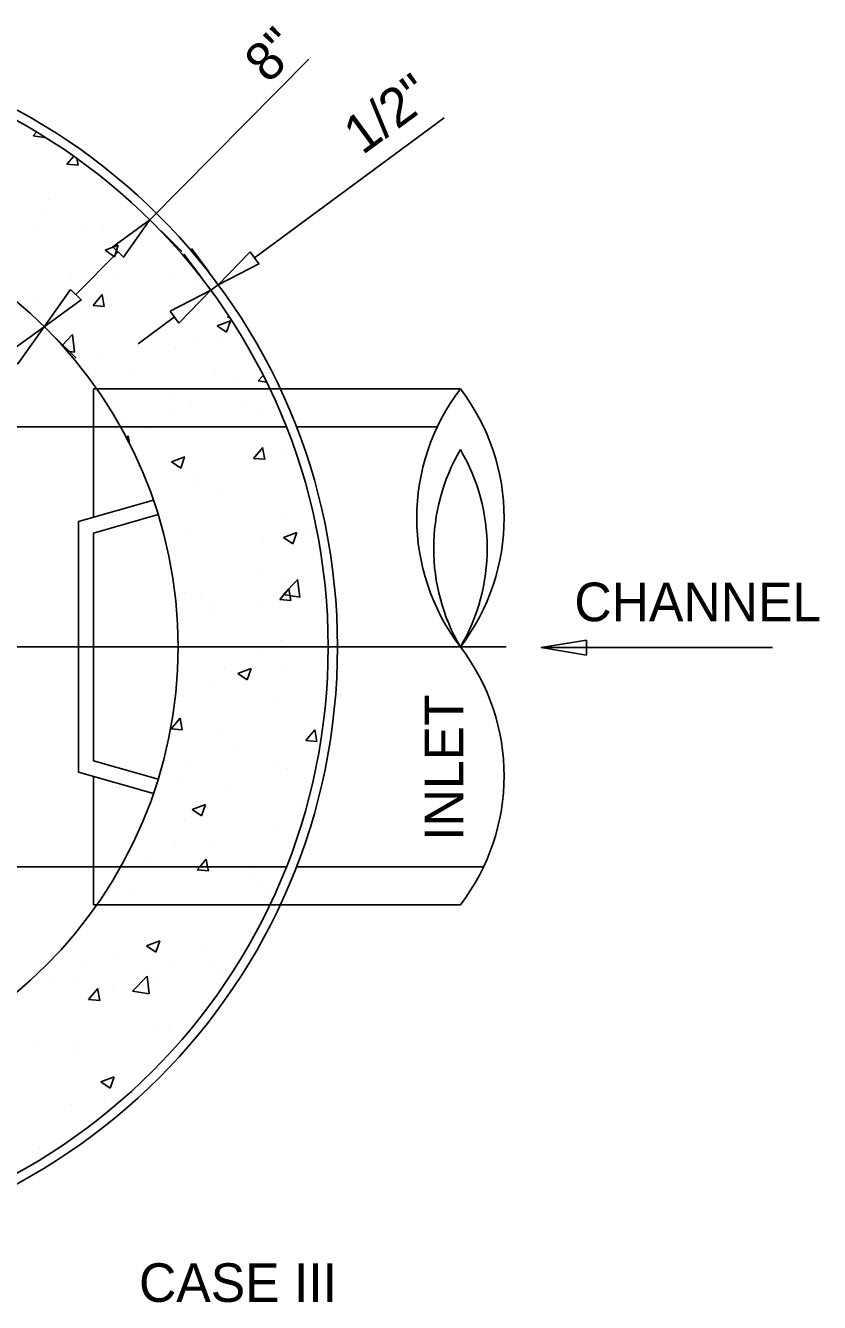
# Model space of a CAD drawing. Extents: x 6712067 to 6713867, y 1867712 to 1869162.
# Drawn here: x 6713040.8 to 6713164.1, y 1867921.8 to 1868120.1 of the extents above; entities that cross this region are included whole.
import ezdxf

# ---------------------------------------------------------------- set-up
doc = ezdxf.new("R2010")
doc.units = 0
for name, color, linetype in [('G-MARK', 7, 'Continuous'), ('G-TEXT', 7, 'Continuous'), ('Misc CnstDet(22)', 7, 'Continuous')]:
    doc.layers.add(name, color=color, linetype=linetype)

msp = doc.modelspace()

# ---------------------------------------------------------------- linework, layer by layer
at = {"layer": 'G-MARK'}
for p, q in [((6713084.83, 1868114.93), (6713060.12, 1868089.94)), ((6713076.38, 1868084.03), (6713105.86, 1868105.8)), ((6713048.64, 1868078.33), (6713055.2, 1868084.97)), ((6713063.95, 1868074.86), (6713058.33, 1868070.7)), ((6713120.94, 1868023.49), (6713156.86, 1868023.49))]:
    msp.add_line(p, q, dxfattribs=at)
at = {"layer": 'G-TEXT'}
for points in [[(6713054.37, 1868085.78), (6713056.02, 1868084.14), (6713060.12, 1868089.94)], [(6713075.69, 1868084.97), (6713077.07, 1868083.1), (6713070.76, 1868079.87)], [(6713047.82, 1868079.15), (6713049.47, 1868077.51), (6713043.72, 1868073.35)], [(6713063.26, 1868075.79), (6713064.64, 1868073.92), (6713069.58, 1868079.01)], [(6713037.97, 1868069.2), (6713039.63, 1868067.56), (6713043.72, 1868073.35)], [(6713127.94, 1868022.32), (6713120.94, 1868023.49), (6713127.94, 1868024.65)]]:
    msp.add_lwpolyline(points, close=True, dxfattribs=at)
at = {"layer": 'Misc CnstDet(22)'}
for p, q in [((6713041.98, 1868102.99), (6713042.54, 1868103.58)), ((6713041.98, 1868102.99), (6713044.02, 1868102.67)), ((6713047.24, 1868098.58), (6713048.3, 1868099.84)), ((6713047.24, 1868098.58), (6713048.99, 1868098.43)), ((6713048.99, 1868098.43), (6713048.79, 1868099.48)), ((6713044.31, 1868093.16), (6713044.31, 1868093.16)), ((6713043.38, 1868091.3), (6713043.38, 1868091.3)), ((6713060.12, 1868089.94), (6713060.12, 1868089.94)), ((6713060.12, 1868089.94), (6713060.12, 1868089.94)), ((6713042.67, 1868088.25), (6713042.67, 1868088.25)), ((6713049.96, 1868089.2), (6713049.96, 1868089.2)), ((6713052.97, 1868088.41), (6713052.97, 1868088.41)), ((6713061.86, 1868088.22), (6713065.09, 1868085.03)), ((6713053.19, 1868085.22), (6713055.22, 1868086)), ((6713054.64, 1868084.23), (6713055.22, 1868086)), ((6713053.19, 1868085.22), (6713054.64, 1868084.23)), ((6713068.13, 1868080.97), (6713065.42, 1868084.64)), ((6713069.3, 1868081.85), (6713066.6, 1868085.51)), ((6713047.92, 1868081.6), (6713047.92, 1868081.6)), ((6713054.51, 1868081.1), (6713054.51, 1868081.1)), ((6713063.48, 1868080.94), (6713063.48, 1868080.94)), ((6713067.35, 1868080.57), (6713067.35, 1868080.57)), ((6713069.58, 1868079.01), (6713070.76, 1868079.87)), ((6713070.76, 1868079.87), (6713070.76, 1868079.87)), ((6713070.76, 1868079.87), (6713070.76, 1868079.87)), ((6713051.3, 1868076.66), (6713052.7, 1868078.33)), ((6713052.63, 1868078.7), (6713052.63, 1868078.7)), ((6713053.04, 1868076.5), (6713052.7, 1868078.33)), ((6713053.34, 1868079.16), (6713053.34, 1868079.16)), ((6713069.58, 1868079.01), (6713069.58, 1868079.01)), ((6713042.3, 1868077.7), (6713042.3, 1868077.7)), ((6713051.3, 1868076.66), (6713053.04, 1868076.51)), ((6713070.59, 1868073.48), (6713072.63, 1868074.26)), ((6713072.03, 1868072.49), (6713072.63, 1868074.26)), ((6713072.21, 1868074.82), (6713072.37, 1868075.03)), ((6713072.21, 1868074.82), (6713072.52, 1868074.8)), ((6713043.72, 1868073.35), (6713043.72, 1868073.35)), ((6713043.72, 1868073.35), (6713043.72, 1868073.35)), ((6713046.5, 1868070.45), (6713048.12, 1868072.15)), ((6713048.44, 1868069.37), (6713048.12, 1868072.14)), ((6713070.59, 1868073.48), (6713072.03, 1868072.5)), ((6713045.46, 1868071.63), (6713048.7, 1868068.44)), ((6713045.46, 1868071.63), (6713048.7, 1868068.44)), ((6713064.08, 1868070.08), (6713064.08, 1868070.08)), ((6713067, 1868070.86), (6713067, 1868070.86)), ((6713071.38, 1868071.05), (6713071.38, 1868071.05)), ((6713047.3, 1868069.55), (6713048.44, 1868069.37)), ((6713052.27, 1868069), (6713052.27, 1868069)), ((6713057.81, 1868066.04), (6713057.81, 1868066.04)), ((6713070.31, 1868066.63), (6713070.31, 1868066.63)), ((6713073.38, 1868065.39), (6713073.38, 1868065.39)), ((6713076.96, 1868064.95), (6713077.75, 1868065.77)), ((6713076.96, 1868064.95), (6713078.25, 1868064.74)), ((6713051.38, 1868043.73), (6713051.38, 1868063.69)), ((6713080.38, 1868063.69), (6713051.38, 1868063.69)), ((6713053.3, 1868063.71), (6713053.3, 1868063.71)), ((6713063.95, 1868062.13), (6713063.95, 1868062.13)), ((6713108.37, 1868063.69), (6713080.38, 1868063.69)), ((6713066.64, 1868061.16), (6713066.64, 1868061.16)), ((6713074.75, 1868061), (6713074.75, 1868061)), ((6713077.29, 1868060.22), (6713077.29, 1868060.22)), ((6713079.52, 1868061.47), (6713079.52, 1868061.47)), ((6713056.41, 1868058.59), (6713056.41, 1868058.59)), ((6713063.71, 1868059.55), (6713063.71, 1868059.55)), ((6713055.59, 1868057.78), (6712993.89, 1868057.78)), ((6713081.33, 1868057.78), (6713055.59, 1868057.78)), ((6713056.49, 1868056.1), (6713056.75, 1868056.4)), ((6713056.97, 1868055.19), (6713056.75, 1868056.4)), ((6713060.29, 1868057.31), (6713060.29, 1868057.31)), ((6713104.77, 1868057.78), (6713082.9, 1868057.78)), ((6713076.24, 1868052.9), (6713077.66, 1868054.58)), ((6713077.99, 1868052.74), (6713077.64, 1868054.58)), ((6713063.49, 1868052.34), (6713065.54, 1868053.12)), ((6713063.49, 1868052.34), (6713064.94, 1868051.36)), ((6713064.94, 1868051.36), (6713065.53, 1868053.12)), ((6713076.24, 1868052.9), (6713077.99, 1868052.75)), ((6713081.42, 1868053.65), (6713081.42, 1868053.65)), ((6713066.28, 1868051.46), (6713066.28, 1868051.46)), ((6713067.57, 1868050.57), (6713067.57, 1868050.57)), ((6713067.08, 1868049.5), (6713067.08, 1868049.5)), ((6713083.13, 1868049.92), (6713083.13, 1868049.92)), ((6713060.68, 1868046.38), (6713049.05, 1868043.07)), ((6713071.42, 1868047.11), (6713071.42, 1868047.11)), ((6713061.41, 1868044.17), (6713051.39, 1868041.3)), ((6713049.05, 1868043.07), (6713049.05, 1868004.15)), ((6713081.06, 1868043.94), (6713081.06, 1868043.94)), ((6713051.39, 1868041.3), (6713051.39, 1868005.91)), ((6713065.93, 1868041.76), (6713065.93, 1868041.76)), ((6713077.82, 1868040.44), (6713077.82, 1868040.44)), ((6713080.89, 1868040.6), (6713082.94, 1868041.39)), ((6713080.89, 1868040.6), (6713082.34, 1868039.62)), ((6713082.34, 1868039.62), (6713082.94, 1868041.38)), ((6713085.12, 1868041.39), (6713085.12, 1868041.39)), ((6713077.46, 1868035.02), (6713077.46, 1868035.02)), ((6713080.71, 1868034.24), (6713080.71, 1868034.24)), ((6713080.3, 1868030.97), (6713081.7, 1868032.65)), ((6713080.82, 1868031.73), (6713083.1, 1868034.09)), ((6713082.03, 1868030.82), (6713081.7, 1868032.65)), ((6713083.41, 1868031.33), (6713083.08, 1868034.09)), ((6713087.22, 1868032.63), (6713087.22, 1868032.63)), ((6713065.57, 1868032.05), (6713065.57, 1868032.05)), ((6713068.04, 1868031.76), (6713068.04, 1868031.76)), ((6713080.3, 1868030.97), (6713082.03, 1868030.82)), ((6713080.82, 1868031.73), (6713083.42, 1868031.33)), ((6713083.6, 1868031.11), (6713083.6, 1868031.11)), ((6713070.15, 1868028.94), (6713070.15, 1868028.94)), ((6713070.22, 1868029.72), (6713070.22, 1868029.72)), ((6713077.45, 1868029.9), (6713077.45, 1868029.9)), ((6713080.35, 1868024.53), (6713080.35, 1868024.53)), ((6712876.34, 1868023.6), (6713115.5, 1868023.6)), ((6713065.22, 1868022.35), (6713065.22, 1868022.35)), ((6713077.21, 1868023.32), (6713077.21, 1868023.32)), ((6713069.78, 1868018.4), (6713069.78, 1868018.4)), ((6713071.65, 1868020.21), (6713071.65, 1868020.21)), ((6713073.8, 1868019.46), (6713075.84, 1868020.25)), ((6713073.8, 1868019.46), (6713075.25, 1868018.49)), ((6713075.25, 1868018.49), (6713075.84, 1868020.25)), ((6713080.82, 1868019.85), (6713080.82, 1868019.85)), ((6713087.22, 1868019.54), (6713087.22, 1868019.54)), ((6713080.01, 1868014.84), (6713080.01, 1868014.84)), ((6713063.43, 1868010.88), (6713064.84, 1868012.55)), ((6713065.17, 1868010.73), (6713064.83, 1868012.55)), ((6713064.86, 1868012.64), (6713064.86, 1868012.64)), ((6713063.43, 1868010.88), (6713065.17, 1868010.73)), ((6713084.34, 1868009.05), (6713085.74, 1868010.73)), ((6713086.08, 1868008.89), (6713085.74, 1868010.72)), ((6713071.34, 1868010.2), (6713071.34, 1868010.2)), ((6713084.34, 1868009.05), (6713086.08, 1868008.89)), ((6713073.16, 1868008.36), (6713073.16, 1868008.36)), ((6713061.41, 1868003.04), (6713051.39, 1868005.91)), ((6713065.99, 1868005.31), (6713065.99, 1868005.31)), ((6713079.65, 1868005.13), (6713079.65, 1868005.13)), ((6713081.55, 1868004.65), (6713081.55, 1868004.65)), ((6713060.68, 1868000.82), (6713049.05, 1868004.15)), ((6713051.38, 1868003.49), (6713051.38, 1867983.53)), ((6713064.5, 1868002.95), (6713064.5, 1868002.95)), ((6713072.12, 1868001.4), (6713072.12, 1868001.4)), ((6713066.71, 1867998.33), (6713068.75, 1867999.11)), ((6713068.15, 1867997.35), (6713068.75, 1867999.11)), ((6713083.9, 1867999.29), (6713083.9, 1867999.29)), ((6713065.48, 1867996.86), (6713065.48, 1867996.86)), ((6713066.71, 1867998.33), (6713068.15, 1867997.35)), ((6713079.3, 1867995.42), (6713079.3, 1867995.42)), ((6713064.16, 1867993.24), (6713064.16, 1867993.24)), ((6713070.14, 1867992.8), (6713070.14, 1867992.8)), ((6713067.87, 1867989.43), (6713068.88, 1867990.63)), ((6713069.1, 1867989.43), (6713068.88, 1867990.62)), ((6713055.59, 1867989.43), (6712989.59, 1867989.43)), ((6713081.33, 1867989.43), (6713055.59, 1867989.43)), ((6713060.18, 1867990.5), (6713060.18, 1867990.5)), ((6713067.48, 1867988.96), (6713067.87, 1867989.43)), ((6713067.48, 1867988.96), (6713069.21, 1867988.8)), ((6713069.21, 1867988.8), (6713069.1, 1867989.43)), ((6713075.74, 1867989.83), (6713075.74, 1867989.83)), ((6713111.97, 1867989.43), (6713082.9, 1867989.43)), ((6713076.22, 1867987.79), (6713076.22, 1867987.79)), ((6713057.81, 1867985.37), (6713057.81, 1867985.37)), ((6713077.12, 1867986.41), (6713077.12, 1867986.41)), ((6713078.94, 1867985.72), (6713078.94, 1867985.72)), ((6713080.38, 1867983.53), (6713051.38, 1867983.53)), ((6713060.12, 1867983.48), (6713060.12, 1867983.48)), ((6713063.8, 1867983.53), (6713063.8, 1867983.53)), ((6713108.37, 1867983.53), (6713080.38, 1867983.53)), ((6713059.62, 1867977.19), (6713061.66, 1867977.97)), ((6713059.62, 1867977.19), (6713061.06, 1867976.21)), ((6713061.06, 1867976.21), (6713061.66, 1867977.97)), ((6713054.51, 1867975.6), (6713054.51, 1867975.6)), ((6713068.56, 1867976.29), (6713068.56, 1867976.29)), ((6713070.07, 1867974.93), (6713070.07, 1867974.93)), ((6713050.15, 1867973.87), (6713050.15, 1867973.87)), ((6713063.45, 1867973.83), (6713063.45, 1867973.83)), ((6713071.25, 1867973.28), (6713071.25, 1867973.28)), ((6713045.09, 1867972.34), (6713045.09, 1867972.34)), ((6713048.73, 1867971.96), (6713048.73, 1867971.96)), ((6713057.44, 1867970.11), (6713059.71, 1867972.48)), ((6713060.03, 1867969.71), (6713059.71, 1867972.48)), ((6713060.65, 1867971.69), (6713060.65, 1867971.69)), ((6713050.61, 1867968.85), (6713052.02, 1867970.53)), ((6713050.61, 1867968.85), (6713052.35, 1867968.7)), ((6713052.35, 1867968.7), (6713052.01, 1867970.53)), ((6713054.26, 1867970.37), (6713054.26, 1867970.37)), ((6713057.44, 1867970.11), (6713060.03, 1867969.71)), ((6713060.89, 1867964.8), (6713060.89, 1867964.8)), ((6713063.09, 1867964.12), (6713063.09, 1867964.12)), ((6713042.48, 1867962.37), (6713042.48, 1867962.37)), ((6713048.37, 1867962.26), (6713048.37, 1867962.26)), ((6713048.7, 1867960.78), (6713048.7, 1867960.78)), ((6713052.52, 1867956.06), (6713054.57, 1867956.84)), ((6713052.52, 1867956.06), (6713053.97, 1867955.08)), ((6713053.97, 1867955.07), (6713054.57, 1867956.84)), ((6713053.05, 1867952.98), (6713053.05, 1867952.98)), ((6713053.22, 1867953.3), (6713053.22, 1867953.3)), ((6713048.01, 1867952.56), (6713048.01, 1867952.56)), ((6713043.03, 1867945.89), (6713043.03, 1867945.89))]:
    msp.add_line(p, q, dxfattribs=at)
msp.add_lwpolyline([(6713108.37, 1868023.6), (6713108.37, 1868023.6)], dxfattribs=at)
for radius in [94.73, 93.28, 69.96]:
    msp.add_circle((6712994.54, 1868023.61), radius, dxfattribs=at)
for centre, radius, start, end in [((6713134.61, 1868043.65), 33.02, 142.6308, 217.3692), ((6713082.13, 1868043.65), 33.02, 322.6308, 37.3692), ((6713134.61, 1868038.93), 30.39, 149.7116, 210.2885), ((6713082.13, 1868038.93), 30.39, 329.7116, 30.2885), ((6713082.13, 1868003.57), 33.02, 322.6308, 37.3692)]:
    msp.add_arc(centre, radius, start, end, dxfattribs=at)

# ---------------------------------------------------------------- texts
for s, rotation, p in [('8"', 45.3287, (6713078.56, 1868110.96)), ('1/2"', 36.4378, (6713093.14, 1868099.92)), ('INLET', 90, (6713108.8, 1867993.49))]:
    msp.add_text(s, height=6, rotation=rotation, dxfattribs=at).set_placement(p)
for s, p in [('CHANNEL', (6713126.07, 1868027.6)), ('CASE III', (6713058.44, 1867921.85))]:
    msp.add_text(s, height=6, dxfattribs=at).set_placement(p)

doc.saveas('drawing.dxf')
